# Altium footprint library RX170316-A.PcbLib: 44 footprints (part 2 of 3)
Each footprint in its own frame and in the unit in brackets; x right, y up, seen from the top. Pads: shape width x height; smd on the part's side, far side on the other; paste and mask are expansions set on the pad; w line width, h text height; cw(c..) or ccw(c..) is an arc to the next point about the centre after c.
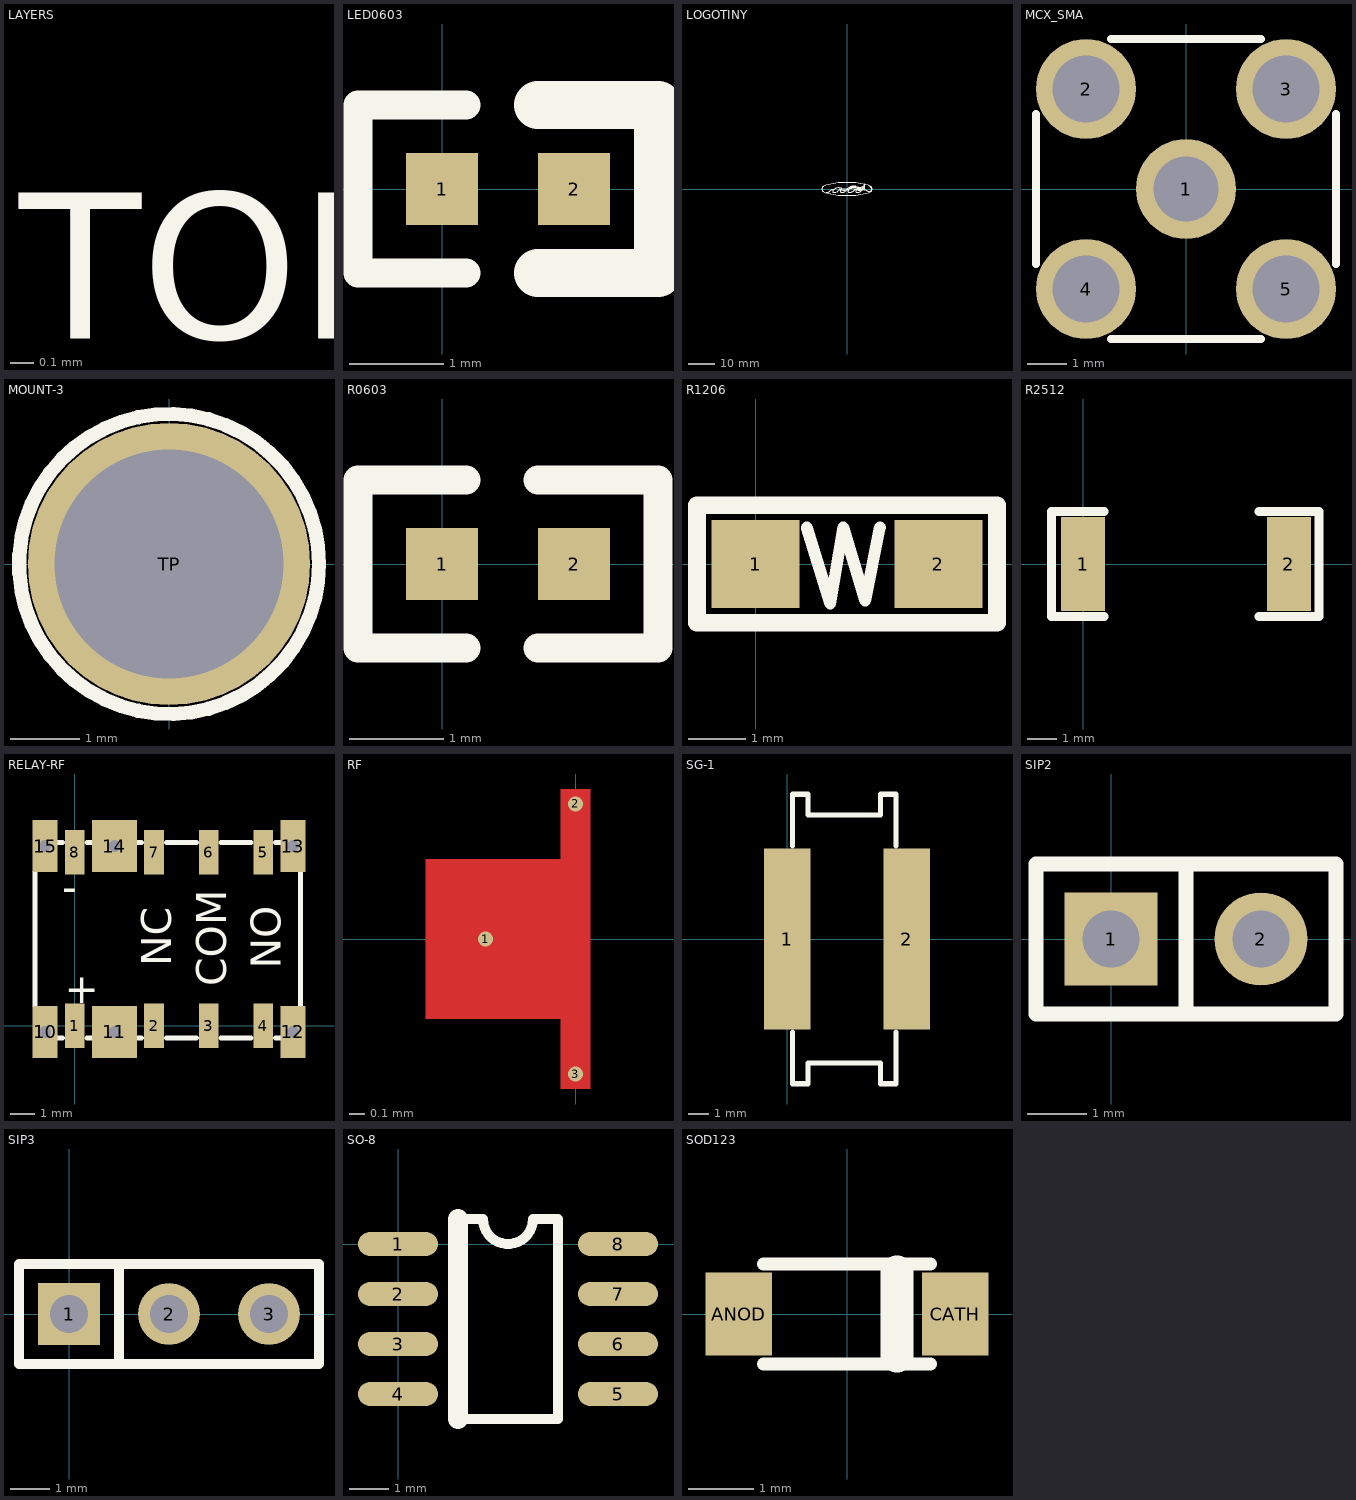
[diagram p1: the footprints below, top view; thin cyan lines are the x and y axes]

## LAYERS [mil]
Top Layer:
  text "TOP" at 25,-75 h50
Bottom Layer:
  text "BOTTOM" at 25,-150 h50
Top Overlay:
  text "TOP OVERLAY" at 25,-225 h50
Top Paste:
  text "TOP PASTE MASK" at 25,-300 h50
Bottom Paste:
  text "BOTTOM PASTE MASK" at 25,-525 h50
Top Solder:
  text "TOP SOLDER MASK" at 25,-375 h50
Bottom Solder:
  text "BOTTOM SOLDER MASK" at 25,-450 h50
Keep-Out Layer:
  text "KEEP OUT" at 25,-600 h50

## LED0603 [mil]
pads (2):
  rect 30x30 smd: 1(0,0) 2(55,0)
Top Overlay:
  lines w12: 10,-35 -35,-35 -35,35 10,35
  lines w20: 40,-35 90,-35 90,35 40,35

## LOGOTINY [mil]
Top Overlay:
  lines w5: -303.97,-50.69 ccw(c-302.5,33.5) -241.93,-24.99 ; -241.63,-25.87 cw(c-205.5,-62) -192.27,-12.64 ; -196.44,-8.91 cw(c-123,-110) -80.26,7.41 ; -191.47,-50.69 ccw(c-190,33.5) -129.43,-24.99 ; -191,-51 cw(c-191,-32) -191,-13 ; -129.13,-25.87 cw(c-93,-62) -79.77,-12.64 ; -85.24,-9.91 ccw(c-42.5,107.5) 30.94,6.41 ; -80.74,7.59 ccw(c-38,125) 35.44,23.91 ; -79,-51 cw(c-79,-32) -79,-13 ; -78.47,-50.19 ccw(c-77,34) -16.43,-24.49 ; -16.63,-25.87 cw(c19.5,-62) 32.73,-12.64 ; 26.56,-11.41 cw(c100,-112.5) 142.74,4.91 ; 26.56,3.59 cw(c100,-97.5) 142.74,19.91 ; 26.56,18.59 cw(c100,-82.5) 142.74,34.91 ; 33.5,-51 cw(c33.5,-32) 33.5,-13 ; 33.53,-50.69 ccw(c35,33.5) 95.57,-24.99 ; 95.87,-25.87 cw(c132,-62) 145.23,-12.64 ; 142.26,-9.91 ccw(c185,107.5) 258.44,6.41 ; 142.26,5.09 ccw(c185,122.5) 258.44,21.41 ; 142.26,20.09 ccw(c185,137.5) 258.44,36.41 ; 142.26,35.09 ccw(c185,152.5) 258.44,51.41 ; 147,-51 cw(c147,-32) 147,-13 ; 147.53,-50.69 ccw(c149,33.5) 209.57,-24.99 ; 206.87,-25.87 cw(c243,-62) 243,-10.9 ; 242.5,-12.5 275,-12.5 ; 257,-12.5 257,77 ; 275.26,-12.78 ccw(c325,27.5) 354.06,-29.52 ; 326.83,45.65 cw(c312,0) 342.21,-37.3
  lines w8: -344.68,-40.96 cw(c-316,0) -344.68,40.96 ; -342.4,-42.61 ccw(c0,1050) 342.4,-42.61 ; -342.4,42.61 cw(c0,-1050) 342.4,42.61 ; 344.68,-40.96 ccw(c316,0) 344.68,40.96

## MCX_SMA [mil]
pads (5):
  round 100 hole 65: 1(0,0)
  round 100 hole 67: 2(-100,100) 3(100,100) 4(-100,-100) 5(100,-100)
Top Overlay:
  lines w8: -150,-75 -150,75 ; -75,-150 75,-150 ; -75,150 75,150 ; 150,-75 150,75

## MOUNT-3 [mil]
pads (1):
  round 160 hole 129.92 mask+5: TP(0,0)
Top Overlay:
  circle w8: c0,0 r85

## PCBComponent_1 [mil]

## R0603 [mil]
pads (2):
  rect 30x30 smd: 1(0,0) 2(55,0)
Top Overlay:
  lines w12: 10,-35 -35,-35 -35,35 10,35 ; 40,-35 90,-35 90,35 40,35

## R1206 [mil]
pads (2):
  rect 60x60 smd: 1(0,0) 2(125,0)
Top Overlay:
  lines w8: 35,25 51,-27 60,25 75,-25 85,25
  lines w12: 130,40 165,40 ; 165,40 -40,40 -40,-40 165,-40 165,40
Top Paste:
  rectangle: -25,-25 25,25
  rectangle: 100,-25 150,25

## R2512 [mm]
pads (2):
  rect 1.5x3.2 smd: 1(0,0) 2(6.985,0)
Top Overlay:
  lines w0.305: 0.711,-1.777 -1.067,-1.777 -1.067,1.779 0.711,1.779 ; 5.969,-1.778 8.001,-1.777 8.001,1.778 5.969,1.778
Top Paste:
  rectangle: 6.223,-1.524 7.747,1.524
  rectangle: -0.762,-1.524 0.762,1.524

## RELAY-RF [mm]
pads (14):
  rect 0.8x1.8 smd: 1(0,0) 2(3.2,0) 3(5.4,0) 4(7.6,0) 5(7.6,7) 6(5.4,7) 7(3.2,7) 8(0,7)
  rect 1x2.1 hole 0.5: 10(-1.2,-0.25) 12(8.8,-0.25) 13(8.8,7.25) 15(-1.2,7.25)
  rect 1.8x2.1 hole 0.5: 11(1.6,-0.25) 14(1.6,7.25)
Top Overlay:
  lines w0.203: -1.6,0.8 -1.6,6.2 ; -0.8,-0.5 -0.5,-0.5 ; -0.8,7.4 -0.5,7.4 ; 0.5,-0.5 0.8,-0.5 ; 0.5,7.4 0.8,7.4 ; 2.3,-0.5 2.7,-0.5 ; 2.3,7.4 2.7,7.4 ; 3.7,-0.5 4.9,-0.5 ; 3.7,7.4 4.9,7.4 ; 5.9,-0.5 7.1,-0.5 ; 5.9,7.4 7.1,7.4 ; 8.1,-0.5 8.3,-0.5 ; 8.1,7.4 8.3,7.4 ; 9.1,0.7 9.1,6.2
  text "+" at -0.4,0.9 h1.2
  text "-" at -0.5,5 h1.2
  text "NO" at 8.3,2.3 h1.2
  text "COM" at 6.1,1.6 h1.2
  text "NC" at 3.9,2.4 h1.2
Top Paste:
  region: 2.286,0.762 0.889,0.762 0.889,-1.27 2.286,-1.27
  region: 3.556,7.874 2.794,7.874 2.794,6.096 3.556,6.096
  region: 5.842,7.874 4.953,7.874 4.953,6.096 5.842,6.096
  region: 8.001,7.874 7.239,7.874 7.239,6.096 8.001,6.096
  region: 8.001,0.889 7.239,0.889 7.239,-0.889 8.001,-0.889
  region: 3.556,0.889 2.794,0.889 2.794,-0.889 3.556,-0.889
  region: 0.381,0.889 -0.381,0.889 -0.381,-0.889 0.381,-0.889
  region: 0.381,7.747 -0.381,7.747 -0.381,6.096 0.381,6.096
  region: 5.842,0.889 4.978,0.889 4.978,-0.889 5.842,-0.889
  region: -0.75,8.25 -1.6,8.25 -1.6,6.325 -0.75,6.325
  region: -0.75,0.775 -1.625,0.775 -1.625,-1.25 -0.75,-1.25
  region: 9.25,8.25 8.35,8.25 8.35,6.25 9.25,6.25
  region: 9.275,0.75 8.4,0.75 8.4,-1.25 9.275,-1.25
  region: 2.286,8.255 0.889,8.255 0.889,6.275 2.286,6.275

## RF [mm]
pads (3):
  round 0.1 smd mask-0.05: 1(-0.6,0) 2(0,0.9) 3(0,-0.9)
Top Layer:
  rectangle: -0.1,-1 0.1,1
  rectangle: -1,-0.532 0,0.532

## SG-1 [mil]
pads (2):
  rect 90x350 smd: 1(0,0) 2(230.31,0)
Top Overlay:
  lines w10: 10,-180 10,-280 40,-280 40,-240 180,-240 180,-280 210,-280 210,-180 ; 10,180 10,280 40,280 40,240 180,240 180,280 210,280 210,180
Top Paste:
  region: -40,170 -40,-170 40,-170 40,170
  region: 190,170 190,-170 270,-170 270,170

## SIP2 [mil]
pads (2):
  rect 62x62 hole 38: 1(0,0)
  round 62 hole 38: 2(100,0)
Top Overlay:
  lines w10: 50,-50 50,50 ; -50,-50 150,-50 150,50 -50,50 -50,-50

## SIP3 [mil]
pads (3):
  rect 62x62 hole 38: 1(0,0)
  round 62 hole 38: 2(100,0) 3(200,0)
Top Overlay:
  lines w10: 50,-50 50,50 ; -50,-50 -50,50 250,50 250,-50 -50,-50

## SO-8 [mil]
pads (8):
  oval 80x24 smd: 1(0,0) 2(0,-50) 3(0,-100) 4(0,-150) 5(220,-150) 6(220,-100) 7(220,-50) 8(220,0)
Top Overlay:
  lines w10: 60,-175 160,-175 160,25 135,25 cw(c110,25) 85,25 60,25
  lines w20: 60,-175 60,25

## SOD123 [mil]
pads (2):
  rect 40x50 smd: ANOD(-65,0) CATH(65,0)
Top Overlay:
  lines w8: -50,-30 50,-30 ; -50,30 50,30
  lines w20: 30,-25 30,25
